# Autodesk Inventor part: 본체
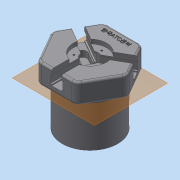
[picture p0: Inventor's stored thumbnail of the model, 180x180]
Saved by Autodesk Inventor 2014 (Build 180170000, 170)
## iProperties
Created: 2023-03
Part Number: 본체
Material: 알루미늄 6061
Document SubType Name: Modeling
Designer: mdu-01
Density: 2.71 g/cm^3
Appearance: 기본값
Author: mdu-01
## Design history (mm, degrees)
sketch "스케치1"
  geometry: C1 r 40 at (0, 0); 1 further point
  constraints: 1 centre point, 1 coincident
  dimensions: "d0" = 80 diameter of C1
extrude "돌출1" new body sketch "스케치1" distance "d1" = 65; taper "d2" = 0 deg
sketch "스케치2"
  geometry: L1 (30.6, 43)-(52.539, 5); L2 (52.539, -5)-(30.6, -43); L3 (21.939, -48)-(-21.939, -48); L4 (-30.6, -43)-(-52.539, -5); L5 (-52.539, 5)-(-30.6, 43); L6 (-21.939, 48)-(21.939, 48); A1 r 10 centre (-43.879, 0) between (-52.539, 5) and (-52.539, -5); A2 r 10 centre (-21.939, -38) between (-30.6, -43) and (-21.939, -48); A3 r 10 centre (21.939, -38) between (21.939, -48) and (30.6, -43); A4 r 10 centre (43.879, 0) between (52.539, -5) and (52.539, 5); A5 r 10 centre (21.939, 38) between (30.6, 43) and (21.939, 48); A6 r 10 centre (-21.939, 38) between (-21.939, 48) and (-30.6, 43); 8 further points
  constraints: 12 end point, 12 point on circle, 12 point on line, 12 tangent, 6 centre point, 5 equal radius, 1 coincident, 1 horizontal alignment, 13 other
  dimensions: "d3" = 96 distance between parallel lines of L3 L6; "d4" = 10 radius of A1
extrude "돌출2" join sketch "스케치2" distance "d5" = 29; taper "d6" = 0 deg
fillet "모깎기1" dims "d7" = 3
sketch "스케치3"
  geometry: L1 (0, 0)-(0, 94); L2 (0, 0)-(25, 0); L3 (25, 0)-(25, 54); L4 (25, 54)-(9, 54); L5 (8, 55)-(8, 57.4); L6 (8, 57.4)-(9.6, 57.4); L7 (10, 57.8)-(10, 60.2); L8 (9.6, 60.6)-(8, 60.6); L9 (8, 60.6)-(8, 63); L10 (9, 64)-(12, 64); L11 (12, 64)-(12, 88); L12 (12, 88)-(24, 88); L13 (24, 88)-(24, 94); L14 (24, 94)-(0, 94); L15 (-21.939, 94)-(21.939, 94) reference; L16 (8, 63)-(9, 64); L17 (8, 55)-(9, 54); A1 r 0.4 centre (9.6, 60.2) between (10, 60.2) and (9.6, 60.6); A2 r 0.4 centre (9.6, 57.8) between (9.6, 57.4) and (10, 57.8); 3 further points
  constraints: 32 end point, 6 parallel, 6 perpendicular, 6 point on line, 4 point on circle, 4 tangent, 2 centre point, 1 collinear, 1 equal radius, 1 midpoint, 1 vertical
  dimensions: "d8" = 50 diameter of L3 L1; "d10" = 48 diameter of L13 L1; "d11" = 6 distance between parallel lines of L12 L14; "d12" = 24 diameter of L11 L1; "d13" = 16 diameter of L9 L1; "d14" = 30 distance between parallel lines of L10 L14; "d15" = 54 distance between parallel lines of L4 L2; "d16" = 5 distance from line of point (10, 59) L4; "d17" = 20 diameter of L7 L1; "d18" = 0.4 radius of A1; "d19" = 3.2 distance between parallel lines of L6 L8; "d20" = 1 distance of L9.end point (8, 64); "d21" = 1 distance of L10.start point (8, 64) (= d20); "d22" = 1 distance of L5.start point (8, 54) (= d20); "d23" = 1 distance of L4.end point (8, 54) (= d22)
revolve "회전1" sketch "스케치3" stored, may be unused: angle "d24" = 90 deg
chamfer "모따기1" distance "d25" = 1; stored, may be unused: second distance "d26" = 2, angle "d27" = 45 deg
sketch "스케치4"
  geometry: L1 (21.939, -91)-(21.939, 3); L2 (29.139, -18)-(29.139, -16.482); L3 (30.939, -16)-(30.939, -5); L4 (29.139, -4.518)-(29.139, 3); L5 (14.739, -18)-(14.739, -16.482); L6 (12.939, -16)-(12.939, -5); L7 (14.739, -4.518)-(14.739, 3); L8 (14.739, 3)-(29.139, 3); L9 (14.739, -18)-(29.139, -18); L10 (43.879, 3)-(0, 3) reference; L11 (12.939, -10.5)-(30.939, -10.5); L12 (29.139, -16.482)-(30.939, -16); L13 (29.139, -4.518)-(30.939, -5); L14 (14.739, -4.518)-(12.939, -5); L15 (14.739, -16.482)-(12.939, -16)
  constraints: 28 end point, 7 symmetric about line, 3 collinear, 3 midpoint, 3 parallel, 1 perpendicular, 1 vertical
  dimensions: "d28" = 14.4 distance between parallel lines of L4 L7; "d30" = 21 distance between parallel lines of L9 L8; "d31" = 11 distance of L3.start L3.end; "d33" = 18 distance between parallel lines of L3 L6; "d34" = 30 deg angle of L12 L13; "d35" = 8 distance from line of L3.end L8
extrude "돌출3" cut sketch "스케치4" stored distance "d36" = 29; taper "d37" = 0 deg
sketch "스케치5" dims "d38" = 34
  geometry: 3 further points
  constraints: 2 vertical alignment, 1 coincident, 2 other
hole "구멍1" sketch "스케치5" at (0, 17) diameter "d39" = 2.459; stored, may be unused: countersink angle "d43" = 90 deg, drill point angle "d45" = 118 deg; dims "d40" = 6, "d41" = 4, "d42" = 2, "d44" = 8
sketch "스케치6"
  geometry: L1 (1.2, 19)-(1.2, 48); L2 (1.2, 48)-(13.2, 48); L3 (13.2, 48)-(13.2, 19); A1 r 6 centre (7.2, 19) between (1.2, 19) and (13.2, 19); 1 further point
  constraints: 6 end point, 2 point on circle, 2 tangent, 2 vertical, 1 centre point, 1 midpoint, 1 perpendicular, 1 vertical alignment
  dimensions: "d46" = 12 diameter of A1; "d48" = 29 distance from line of A1.centre L2
extrude "돌출4" cut sketch "스케치6" stored distance "d49" = 29; taper "d50" = 0 deg
sketch "스케치7"
  geometry: L1 (-12.49, -38)-(12.49, -38); A1 r 40 centre (0, 0) between (-12.49, -38) and (12.49, -38) reference; 1 further point
  constraints: 2 end point, 2 point on circle, 1 horizontal
  dimensions: "d54" = 38 distance from line of L1 A1.centre
extrude "돌출5" cut sketch "스케치7" distance "d55" = 57; taper "d56" = 0 deg
sketch "스케치8"
  geometry: L1 (24.98, 0)-(0, 0) reference; C1 r 2 at (12.49, 16); C2 r 2 at (12.49, 49); 2 further points
  constraints: 2 centre point, 2 vertical alignment, 1 midpoint
  dimensions: "d57" = 4 diameter of C1; "d58" = 4 diameter of C2; "d59" = 16 distance from line of C1.centre L1; "d60" = 33 distance of C1.centre C2.centre
extrude "돌출6" cut sketch "스케치8" stored distance "d61" = 29; taper "d62" = 0 deg
hole "구멍2" sketch "스케치8" diameter "d63" = 8; stored, may be unused: countersink angle "d67" = 90 deg, drill point angle "d69" = 118 deg; dims "d64" = 9, "d65" = 4, "d66" = 2, "d68" = 11, "d81" = 0.62479, "d82" = 7.985
sketch "스케치9" dims "d70" = 64
  geometry: 3 further points
  constraints: 2 vertical alignment, 1 coincident, 2 other
hole "구멍3" sketch "스케치9" at (0, -32) diameter "d71" = 3.242; stored, may be unused: countersink angle "d75" = 90 deg, drill point angle "d77" = 118 deg; dims "d72" = 6, "d73" = 4, "d74" = 2, "d76" = 8
sketch "스케치10"
  geometry: L1 (21.939, 48)-(-21.939, 48) reference; 2 further points
  constraints: 1 vertical alignment, 1 other
  dimensions: "d83" = 10 distance from line of point (0, 38) L1
feature "엠보싱1" sketch "스케치10" dims "d3" = 96, "d4" = 10, "d84" = 0.5, "d85" = 0
node "작업 평면1"
node "작업 평면2"
node "작업 평면3"
node "작업 평면4"
node "솔리드1"
pattern_circular "원형 패턴1" dims "d52" = 360 deg
pattern_circular "원형 패턴2" dims angle "d79" = 360 deg
